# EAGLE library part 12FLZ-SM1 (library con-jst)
CONNECTOR
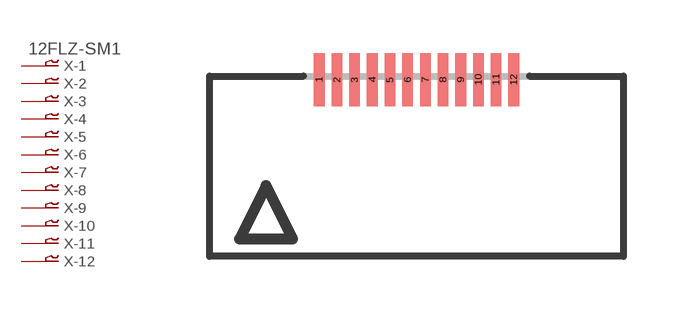
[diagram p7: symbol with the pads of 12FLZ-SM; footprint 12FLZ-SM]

Designator prefix X; gates -1=P-VN -2=P-N -3=P-N -4=P-N -5=P-N -6=P-N -7=P-N -8=P-N -9=P-N -10=P-N -11=P-N -12=P-N

## 12FLZ-SM1 (OC_FARNELL: unknown; OC_NEWARK: unknown)  [12FLZ-SM]
1  -1:1  pas
2  -2:1  pas
3  -3:1  pas
4  -4:1  pas
5  -5:1  pas
6  -6:1  pas
7  -7:1  pas
8  -8:1  pas
9  -9:1  pas
10  -10:1  pas
11  -11:1  pas
12  -12:1  pas

## Footprint 12FLZ-SM (pad centres in mm)
CONNECTOR
smd 0.3 x 1.5: 1 -2.75,2.5; 2 -2.25,2.5; 3 -1.75,2.5; 4 -1.25,2.5; 5 -0.75,2.5; 6 -0.25,2.5; 7 0.25,2.5; 8 0.75,2.5; 9 1.25,2.5; 10 1.75,2.5; 11 2.25,2.5; 12 2.75,2.5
